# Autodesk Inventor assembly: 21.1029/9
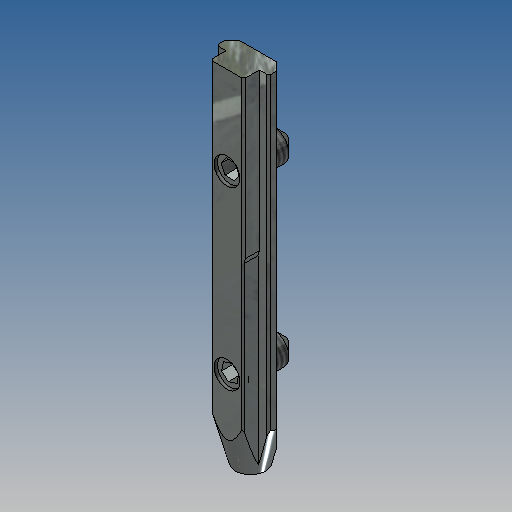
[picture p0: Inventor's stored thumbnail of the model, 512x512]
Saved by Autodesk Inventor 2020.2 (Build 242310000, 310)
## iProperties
Created: 2006-12
Part Number: 21.1029/9
Document SubType Name: Assembly
Designer: Andy Moles
Mass: 62.769 g
Surface Area: 48.122 cm^2
Volume: 7.99469 cm^3
Density: 7.85134 g/cm^3
Description: SLIDE IN T-SLOT BAR 45
Vendor: S
Author: Andy Moles
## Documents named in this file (3)
- Y:\INVENTOR LIBRARIES\PARTS LIBRARY\FASTENING ELEMENTS\21.1029_9 SLIDE IN T-SLOT BAR 45.iam
- Y:\INVENTOR LIBRARIES\PARTS LIBRARY\FASTENING ELEMENTS\SET SCREWS\21.1303 M8X14 T-SLOT BAR SET SCREW.ipt
- Y:\INVENTOR LIBRARIES\PARTS LIBRARY\FASTENING ELEMENTS\SUBCOMPONENTS\21.1029_9 SLIDE IN T-SLOT BAR 45.ipt
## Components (3 placed, 2 different names)
1. 21.1029_9 SLIDE IN T-SLOT BAR 45:1 — Flush:1, Mate:1, Mate:2, Mate:5, Flush:2
2. 21.1303 M8X14 T-SLOT BAR SET SCREW:1 — Mate:1
3. 21.1303 M8X14 T-SLOT BAR SET SCREW:2 — Mate:2
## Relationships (5: Mate 3, Flush 2)
- Flush:1: 21.1029_9 SLIDE IN T-SLOT BAR 45:1
- Mate:1: 21.1029_9 SLIDE IN T-SLOT BAR 45:1 ↔ 21.1303 M8X14 T-SLOT BAR SET SCREW:1
- Mate:2: 21.1029_9 SLIDE IN T-SLOT BAR 45:1 ↔ 21.1303 M8X14 T-SLOT BAR SET SCREW:2
- Mate:5: 21.1029_9 SLIDE IN T-SLOT BAR 45:1
- Flush:2: 21.1029_9 SLIDE IN T-SLOT BAR 45:1
